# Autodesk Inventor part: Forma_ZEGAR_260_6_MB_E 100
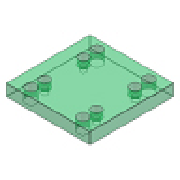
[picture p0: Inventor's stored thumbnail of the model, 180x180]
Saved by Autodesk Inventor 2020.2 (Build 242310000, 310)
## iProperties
Manager: www.cadconsulting.pl
Company: Fabian Stasiak CAD Consulting
IsCustomPart: 1
Created: 2014-02
Part Number: Forma_ZEGAR_260_6_MB_E 100
Material: S 55 C
Description: Top Clamping Plate
Document SubType Name: Modeling
Designer: F.Stasiak
Standard Revision: 1
Manufacturer: DME
Language: pl-PL
Size Designation: 496x396x27
Categories: <MemberInstance><Categories><Category DisplayName="Forma wtryskowa" InternalName="349578f2-f4d4-4954-8c09-8e99297a61c0" Mnemonic="MOLD"><Category DisplayName="P
Density: 7.85 g/cm^3
Appearance: Clear - Green 1
Catalog Web Link: www.expertbooks.pl
Author: F.Stasiak
Subject: Zbiór ćwiczeń. Autodesk Inventor 2020. Kurs Professional
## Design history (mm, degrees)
sketch "Sketch1"
  geometry: L1 (-198, 248)-(198, 248); L2 (198, 248)-(198, -248); L3 (198, -248)-(-198, -248); L4 (-198, -248)-(-198, 248); 3 further points
  constraints: 8 end point, 2 midpoint, 2 parallel, 1 horizontal, 1 horizontal alignment, 1 perpendicular, 1 vertical alignment
  dimensions: "d102" = 396 distance between parallel lines of L2 L4 (= W_); "d103" = 496 distance between parallel lines of L3 L1 (= L)
extrude "Extrusion1" new body sketch "Sketch1" distance "d20" = 27 (= H_); taper "d30" = 0 deg
sketch "Sketch2"
  geometry: 3 further points
  dimensions: "d72" = 137 horizontal distance of point (0, 0) point (-137, 165) (= 0.5 x S1_W); "d73" = 137 horizontal distance of point (0, 0) point (-137, 208) (= 0.5 x GP_W); "d74" = 208 vertical distance of point (0, 0) point (-137, 208) (= 0.5 x GP_L); "d75" = 165 vertical distance of point (0, 0) point (-137, 165) (= 0.5 x S1_L)
hole "Hole1" sketch "Sketch2" diameter "d76" = 42 (= GP_d1); stored, may be unused: countersink angle "d80" = 90 deg, drill point angle "d82" = 0 deg; dims "d77" = 6, "d78" = 4, "d79" = 2, "d81" = 27 (= H_)
pattern_linear "Rectangular Pattern1" dims "d98" = 416 (computed from GP_L, Nl), "d101" = 274 (computed from GP_W, Nw)
hole "Hole2" sketch "Sketch2" diameter "d83" = 18 (= S1_d1); stored, may be unused: countersink angle "d87" = 90 deg, drill point angle "d89" = 0 deg; dims "d84" = 6, "d85" = 26 (= S1_d2), "d86" = 21 (= S1_k), "d88" = 27 (= H_)
pattern_linear "Rectangular Pattern2" dims "d92" = 330 (computed from S1_L, Ns), "d95" = 274 (computed from S1_W, Nw)
chamfer "Chamfer1" distance "d104" = 0.5; stored, may be unused: second distance "d105" = 2, angle "d106" = 45 deg
node "Płaszczyzna konstrukcyjna2"
node "Płaszczyzna konstrukcyjna3"
node "Płaszczyzna konstrukcyjna4"
node "Płaszczyzna konstrukcyjna5"
feature "Rzeźbienie1"
body "Solid1"
feature "Powierzchnia1"
body "Srf1"
other parameters: "L" = 496 [user parameter; used in 1 equation term], "W_" = 396 [user parameter; used in 1 equation term], "H_" = 27 [user parameter; used in 3 equation terms], "S1_W" = 274 [user parameter; used in 2 equation terms], "S1_d1" = 18 [user parameter; used in 1 equation term], "S1_d2" = 26 [user parameter; used in 1 equation term], "S1_k" = 21 [user parameter; used in 1 equation term], "GP_d1" = 42 [user parameter; used in 1 equation term], "GP_W" = 274 [user parameter; used in 2 equation terms], "GP_L" = 416 [user parameter; used in 2 equation terms]
